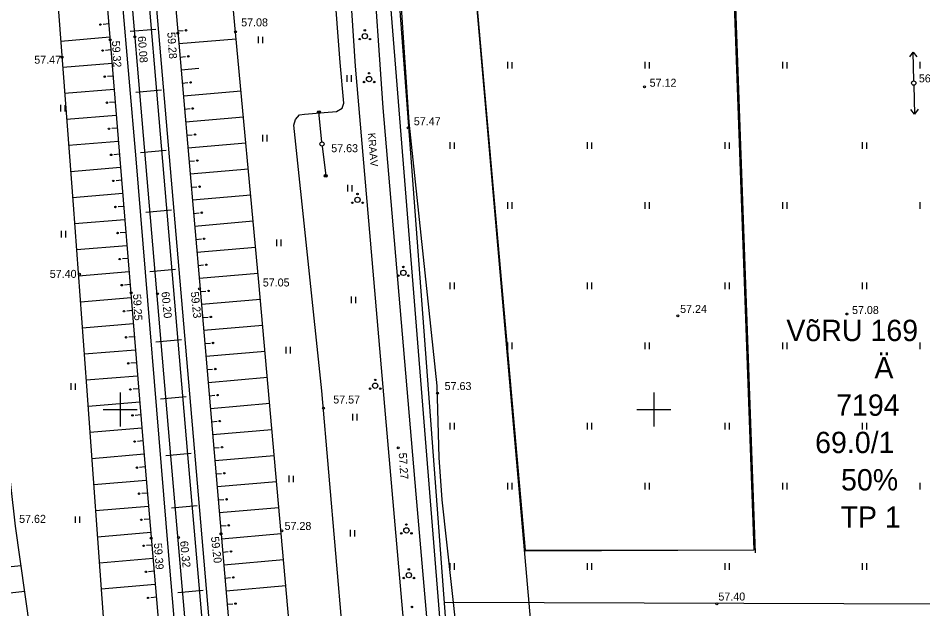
# Model space of a CAD drawing. Extents: x 9156 to 9809, y 2728 to 4000.
# Drawn here: x 9290.4 to 9375.2, y 3581.3 to 3636.7 of the extents above; entities that cross this region are included whole.
import ezdxf

# ---------------------------------------------------------------- set-up
doc = ezdxf.new("R2010")
doc.units = 0
for name, color, linetype in [('Level 1', 7, 'Continuous'), ('Level 11', 7, 'Continuous'), ('Level 5', 7, 'Continuous'), ('Level 54', 7, 'Continuous'), ('Level 58', 7, 'Continuous'), ('Level 6', 7, 'Continuous'), ('Level 7', 7, 'Continuous')]:
    doc.layers.add(name, color=color, linetype=linetype)

# ---------------------------------------------------------------- blocks, each defined once
blk = doc.blocks.new('KKOL')
at = {"layer": 'Level 58'}
for p, q in [((0, 1.59349), (0, -1.5935)), ((-1.5935, 0), (1.59349, 0))]:
    blk.add_line(p, q, dxfattribs=at)

msp = doc.modelspace()

# ---------------------------------------------------------------- linework, layer by layer
at = {"layer": 'Level 1'}
msp.add_line((9347.38, 3362.85), (9317.65, 3734.12), dxfattribs=at)
msp.add_line((9347.38, 3362.85), (9317.65, 3734.12), dxfattribs=at)
at = {"layer": 'Level 11'}
for points in [[(9328.17, 3697.177), (9337.927, 3586.83), (9359.389, 3586.857), (9356.831, 3657.924), (9386.375, 3658.386), (9385.932, 3691.773)], [(9328.17, 3697.177), (9337.927, 3586.771), (9359.389, 3586.857), (9356.831, 3657.924), (9386.375, 3658.386), (9385.932, 3691.773)]]:
    msp.add_lwpolyline(points, close=True, dxfattribs=at)
at = {"layer": 'Level 54'}
for p, q in [((9297.624, 3704.585), (9307.22, 3593.093)), ((9301.488, 3623.507), (9296.984, 3675.228)), ((9325.553, 3648.898), (9327.039, 3626.936)), ((9298.927, 3636.154), (9298.403, 3636.11)), ((9294.421, 3634.544), (9299.03, 3634.932)), ((9300.927, 3635.459), (9303.326, 3635.676)), ((9305.386, 3635.494), (9305.909, 3635.539)), ((9312.93, 3634.964), (9312.93, 3634.344)), ((9313.335, 3634.953), (9313.335, 3634.344)), ((9310.868, 3634.737), (9305.491, 3634.273)), ((9299.13, 3633.711), (9298.606, 3633.668)), ((9373.976, 3633.063), (9374.301, 3633.507)), ((9374.341, 3630.807), (9374.301, 3633.507)), ((9374.301, 3633.507), (9374.638, 3633.073)), ((9294.607, 3632.111), (9299.23, 3632.49)), ((9305.597, 3633.052), (9306.121, 3633.097)), ((9336.272, 3632.595), (9336.272, 3631.975)), ((9336.677, 3632.584), (9336.677, 3631.975)), ((9349.153, 3632.595), (9349.153, 3631.975)), ((9349.559, 3632.584), (9349.559, 3631.975)), ((9362.035, 3632.595), (9362.035, 3631.975)), ((9362.44, 3632.584), (9362.44, 3631.975)), ((9374.916, 3632.595), (9374.916, 3631.975)), ((9307.37, 3631.975), (9305.702, 3631.831)), ((9299.33, 3631.268), (9298.806, 3631.225)), ((9305.808, 3630.61), (9306.332, 3630.655)), ((9321.223, 3631.351), (9321.223, 3630.731)), ((9321.629, 3631.34), (9321.629, 3630.731)), ((9294.793, 3629.667), (9299.43, 3630.047)), ((9301.466, 3629.759), (9303.865, 3629.976)), ((9311.322, 3629.856), (9305.913, 3629.389)), ((9374.35, 3630.407), (9374.424, 3627.708)), ((9294.407, 3628.561), (9294.407, 3627.941)), ((9294.812, 3628.549), (9294.812, 3627.941)), ((9299.53, 3628.825), (9299.006, 3628.782)), ((9306.019, 3628.167), (9306.543, 3628.213)), ((9374.424, 3627.708), (9374.081, 3628.138)), ((9374.743, 3628.156), (9374.424, 3627.708)), ((9294.979, 3627.223), (9299.63, 3627.604)), ((9311.55, 3627.415), (9306.124, 3626.946)), ((9318.885, 3625.098), (9318.614, 3627.885)), ((9327.039, 3626.936), (9329.675, 3602.225)), ((9299.73, 3626.382), (9299.206, 3626.339)), ((9306.23, 3625.725), (9306.754, 3625.771)), ((9313.338, 3625.76), (9313.338, 3625.14)), ((9313.743, 3625.749), (9313.743, 3625.14)), ((9295.165, 3624.779), (9299.83, 3625.161)), ((9311.777, 3624.975), (9306.336, 3624.504)), ((9318.928, 3624.7), (9319.251, 3621.919)), ((9330.866, 3625.064), (9330.866, 3624.444)), ((9331.272, 3625.053), (9331.272, 3624.444)), ((9343.748, 3625.064), (9343.748, 3624.444)), ((9344.153, 3625.053), (9344.153, 3624.444)), ((9356.629, 3625.064), (9356.629, 3624.444)), ((9357.035, 3625.053), (9357.035, 3624.444)), ((9369.511, 3625.064), (9369.511, 3624.444)), ((9369.916, 3625.053), (9369.916, 3624.444)), ((9299.929, 3623.939), (9299.405, 3623.896)), ((9301.906, 3624.108), (9304.305, 3624.325)), ((9304.523, 3586.699), (9301.488, 3623.507)), ((9306.441, 3623.283), (9306.965, 3623.329)), ((9295.351, 3622.335), (9300.029, 3622.718)), ((9312.004, 3622.534), (9306.547, 3622.062)), ((9300.129, 3621.496), (9299.605, 3621.453)), ((9306.652, 3620.841), (9307.176, 3620.887)), ((9321.291, 3621.066), (9321.291, 3620.445)), ((9321.697, 3621.054), (9321.697, 3620.445)), ((9295.538, 3619.891), (9300.229, 3620.275)), ((9312.232, 3620.094), (9306.758, 3619.62)), ((9300.329, 3619.053), (9299.805, 3619.01)), ((9336.272, 3619.444), (9336.272, 3618.824)), ((9336.677, 3619.433), (9336.677, 3618.824)), ((9349.153, 3619.444), (9349.153, 3618.824)), ((9349.559, 3619.433), (9349.559, 3618.824)), ((9362.035, 3619.444), (9362.035, 3618.824)), ((9362.44, 3619.433), (9362.44, 3618.824)), ((9374.916, 3619.444), (9374.916, 3618.824)), ((9302.396, 3618.506), (9304.795, 3618.724)), ((9306.863, 3618.399), (9307.387, 3618.445)), ((9295.72, 3617.446), (9300.429, 3617.832)), ((9312.459, 3617.653), (9306.969, 3617.178)), ((9294.475, 3616.766), (9294.475, 3616.146)), ((9294.88, 3616.755), (9294.88, 3616.146)), ((9300.529, 3616.61), (9300.005, 3616.567)), ((9295.901, 3615.002), (9300.629, 3615.389)), ((9307.075, 3615.957), (9307.598, 3616.003)), ((9314.629, 3615.952), (9314.629, 3615.332)), ((9315.034, 3615.941), (9315.034, 3615.332)), ((9312.686, 3615.212), (9307.18, 3614.736)), ((9300.729, 3614.167), (9300.205, 3614.124)), ((9296.083, 3612.557), (9300.829, 3612.946)), ((9302.786, 3612.949), (9305.185, 3613.167)), ((9307.286, 3613.515), (9307.809, 3613.561)), ((9312.913, 3612.772), (9307.391, 3612.294)), ((9300.929, 3611.724), (9300.405, 3611.681)), ((9330.866, 3611.913), (9330.866, 3611.293)), ((9331.272, 3611.902), (9331.272, 3611.293)), ((9343.748, 3611.913), (9343.748, 3611.293)), ((9344.153, 3611.902), (9344.153, 3611.293)), ((9356.629, 3611.913), (9356.629, 3611.293)), ((9357.035, 3611.902), (9357.035, 3611.293)), ((9369.511, 3611.913), (9369.511, 3611.293)), ((9369.916, 3611.902), (9369.916, 3611.293)), ((9296.264, 3610.113), (9301.029, 3610.503)), ((9307.497, 3611.073), (9308.021, 3611.118)), ((9313.134, 3610.328), (9307.602, 3609.852)), ((9321.632, 3610.592), (9321.632, 3609.972)), ((9322.038, 3610.581), (9322.038, 3609.972)), ((9301.128, 3609.281), (9300.604, 3609.238)), ((9307.707, 3608.631), (9308.231, 3608.676)), ((9296.445, 3607.668), (9301.228, 3608.06)), ((9313.351, 3607.887), (9307.812, 3607.41)), ((9301.328, 3606.838), (9300.804, 3606.795)), ((9303.325, 3606.364), (9305.724, 3606.582)), ((9307.917, 3606.189), (9308.441, 3606.234)), ((9336.272, 3606.293), (9336.272, 3605.673)), ((9336.677, 3606.282), (9336.677, 3605.673)), ((9349.153, 3606.293), (9349.153, 3605.673)), ((9349.559, 3606.282), (9349.559, 3605.673)), ((9362.035, 3606.293), (9362.035, 3605.673)), ((9362.44, 3606.282), (9362.44, 3605.673)), ((9374.916, 3606.293), (9374.916, 3605.673)), ((9296.626, 3605.224), (9301.428, 3605.617)), ((9313.567, 3605.445), (9308.022, 3604.968)), ((9315.514, 3605.887), (9315.514, 3605.267)), ((9315.919, 3605.876), (9315.919, 3605.267)), ((9301.528, 3604.395), (9301.004, 3604.352)), ((9308.127, 3603.747), (9308.651, 3603.792)), ((9296.807, 3602.779), (9301.628, 3603.174)), ((9313.784, 3603.004), (9308.232, 3602.526)), ((9295.358, 3602.474), (9295.358, 3601.854)), ((9295.764, 3602.462), (9295.764, 3601.854)), ((9301.728, 3601.952), (9301.204, 3601.909)), ((9329.675, 3602.225), (9329.847, 3595.503)), ((9300, 3601.25), (9300, 3598.75)), ((9303.766, 3601.008), (9306.165, 3601.226)), ((9308.337, 3601.305), (9308.861, 3601.35)), ((9350, 3601.25), (9350, 3598.75)), ((9296.985, 3600.335), (9301.828, 3600.731)), ((9314.001, 3600.562), (9308.442, 3600.084)), ((9298.75, 3600), (9301.25, 3600)), ((9301.928, 3599.509), (9301.404, 3599.466)), ((9321.768, 3599.615), (9321.768, 3598.995)), ((9322.173, 3599.604), (9322.173, 3598.995)), ((9348.75, 3600), (9351.25, 3600)), ((9308.548, 3598.863), (9309.071, 3598.908)), ((9330.866, 3598.762), (9330.866, 3598.142)), ((9331.272, 3598.75), (9331.272, 3598.142)), ((9343.748, 3598.762), (9343.748, 3598.142)), ((9344.153, 3598.75), (9344.153, 3598.142)), ((9356.629, 3598.762), (9356.629, 3598.142)), ((9357.035, 3598.75), (9357.035, 3598.142)), ((9369.511, 3598.762), (9369.511, 3598.142)), ((9369.916, 3598.75), (9369.916, 3598.142)), ((9297.162, 3597.89), (9302.028, 3598.288)), ((9314.217, 3598.121), (9308.653, 3597.642)), ((9302.128, 3597.066), (9301.604, 3597.021)), ((9304.256, 3595.701), (9306.655, 3595.919)), ((9308.758, 3596.421), (9309.282, 3596.466)), ((9297.34, 3595.424), (9302.233, 3595.845)), ((9314.434, 3595.679), (9308.863, 3595.2)), ((9329.847, 3595.503), (9330.133, 3591.538)), ((9302.338, 3594.624), (9301.815, 3594.579)), ((9297.516, 3592.979), (9302.444, 3593.403)), ((9308.968, 3593.978), (9309.492, 3594.024)), ((9315.786, 3593.82), (9315.786, 3593.2)), ((9316.191, 3593.809), (9316.191, 3593.2)), ((9314.651, 3593.237), (9309.073, 3592.757)), ((9336.272, 3593.142), (9336.272, 3592.521)), ((9336.677, 3593.13), (9336.677, 3592.521)), ((9349.153, 3593.142), (9349.153, 3592.521)), ((9349.559, 3593.13), (9349.559, 3592.521)), ((9362.035, 3593.142), (9362.035, 3592.521)), ((9362.44, 3593.13), (9362.44, 3592.521)), ((9374.916, 3593.142), (9374.916, 3592.521)), ((9302.549, 3592.182), (9302.025, 3592.137)), ((9297.693, 3590.534), (9302.654, 3590.961)), ((9304.795, 3590.787), (9307.194, 3591.005)), ((9309.178, 3591.536), (9309.702, 3591.581)), ((9314.867, 3590.796), (9309.283, 3590.315)), ((9330.133, 3591.538), (9331.678, 3577.558)), ((9295.766, 3589.997), (9295.766, 3589.377)), ((9296.172, 3589.986), (9296.172, 3589.377)), ((9302.759, 3589.74), (9302.235, 3589.695)), ((9309.388, 3589.094), (9309.912, 3589.139)), ((9297.87, 3588.089), (9302.865, 3588.519)), ((9315.084, 3588.354), (9309.493, 3587.873)), ((9321.535, 3588.725), (9321.535, 3588.105)), ((9321.941, 3588.714), (9321.941, 3588.105)), ((9302.97, 3587.298), (9302.446, 3587.253)), ((9307.95, 3547.291), (9304.523, 3586.699)), ((9309.598, 3586.652), (9310.122, 3586.697)), ((9298.046, 3585.644), (9303.075, 3586.077)), ((9315.301, 3585.913), (9309.704, 3585.431)), ((9290.721, 3585.374), (9282.2, 3584.493)), ((9330.866, 3585.61), (9330.866, 3584.99)), ((9331.272, 3585.599), (9331.272, 3584.99)), ((9343.748, 3585.61), (9343.748, 3584.99)), ((9344.153, 3585.599), (9344.153, 3584.99)), ((9356.629, 3585.61), (9356.629, 3584.99)), ((9357.035, 3585.599), (9357.035, 3584.99)), ((9369.511, 3585.61), (9369.511, 3584.99)), ((9369.916, 3585.599), (9369.916, 3584.99)), ((9303.18, 3584.856), (9302.656, 3584.811)), ((9309.809, 3584.21), (9310.332, 3584.255)), ((9298.223, 3583.199), (9303.285, 3583.635)), ((9315.517, 3583.471), (9309.914, 3582.989)), ((9291.061, 3582.945), (9282.452, 3582.055)), ((9303.391, 3582.414), (9302.867, 3582.369)), ((9305.381, 3582.857), (9307.78, 3583.075)), ((9310.019, 3581.768), (9310.543, 3581.813))]:
    msp.add_line(p, q, dxfattribs=at)
for points in [[(9291.142, 3750), (9292.509, 3734.326), (9298.237, 3671.484), (9304.697, 3595.661), (9311.403, 3518.763), (9313.026, 3500)], [(9292.749, 3750), (9294.103, 3734.468), (9299.832, 3671.625), (9306.292, 3595.799), (9312.998, 3518.901), (9314.633, 3500)], [(9289.521, 3722.865), (9289.636, 3711.949), (9290.094, 3696.436), (9293.302, 3649.242), (9295.59, 3619.198), (9296.851, 3602.192), (9300.163, 3556.342), (9301.424, 3542.094), (9302.684, 3538.991), (9304.632, 3528.075), (9306.915, 3513.758), (9308.634, 3504.221), (9309.025, 3500)], [(9291.411, 3723.027), (9293.543, 3697.334), (9296.97, 3659.378), (9299.033, 3634.903), (9302.12, 3597.158), (9303.724, 3578.543), (9308.876, 3518.425), (9310.547, 3500)], [(9298.789, 3500), (9298.217, 3515.72), (9298.103, 3526.407), (9296.155, 3540.196), (9294.785, 3549.211), (9292.952, 3569.435), (9290.202, 3589.084), (9286.767, 3619.468), (9285.736, 3621.307), (9285.048, 3622.915), (9284.705, 3624.754), (9285.736, 3627.512), (9286.423, 3629.465), (9282.989, 3666.871), (9279.667, 3687.502), (9279.324, 3696.006), (9278.522, 3701.406), (9275.886, 3702.9), (9273.137, 3704.049)], [(9338.258, 3687.747), (9322.788, 3689.022), (9307.371, 3689.607), (9301.808, 3689.766), (9301.118, 3689.66), (9300.588, 3689.394), (9305.358, 3635.801), (9307.477, 3611.291), (9311.555, 3563.906), (9317.681, 3500)], [(9322.827, 3500), (9320.981, 3519.574), (9317.172, 3564.824), (9312.99, 3611.945), (9310.716, 3636.371), (9308.332, 3662.194), (9306.003, 3685.955), (9306.268, 3686.115), (9314.533, 3685.69)], [(9320.59, 3632.541), (9317.733, 3670.104), (9317.548, 3671.911), (9317.044, 3672.043), (9314.131, 3672.043), (9313.177, 3672.309), (9312.647, 3673.903), (9312.753, 3675.869), (9313.548, 3676.56), (9315.084, 3676.56), (9316.991, 3676.772), (9317.415, 3677.729), (9316.938, 3683.892)], [(9318.454, 3683.747), (9319.718, 3666.857), (9322.009, 3632.198), (9324.759, 3600.294), (9328.879, 3553.079), (9332.486, 3509.644), (9333.576, 3500)], [(9335.945, 3500), (9334.833, 3509.401), (9333.86, 3522.52), (9332.198, 3540.675), (9327.731, 3592.08), (9324.641, 3628.274), (9322.58, 3658.051), (9320.287, 3683.565)], [(9316.248, 3626.653), (9316.408, 3627.198), (9316.805, 3627.623), (9317.256, 3627.703), (9319.11, 3627.862), (9320.249, 3627.942), (9320.779, 3628.26), (9320.938, 3628.739), (9320.59, 3632.541)], [(9325.777, 3525.127), (9323.47, 3548.394), (9318.897, 3601.758), (9316.248, 3626.653)], [(9307.22, 3593.093), (9313.584, 3518.487), (9315.454, 3500)]]:
    msp.add_lwpolyline(points, dxfattribs=at)
for centre, radius in [((9298.148, 3636.096), 0.0683), ((9301.374, 3634.935), 0.0909), ((9305.384, 3635.276), 0.0909), ((9306.165, 3635.553), 0.0683), ((9310.793, 3635.406), 0.0909), ((9322.916, 3635.003), 0.25), ((9322.916, 3635.553), 0.0707), ((9299.062, 3634.662), 0.0909), ((9322.439, 3634.728), 0.0707), ((9323.392, 3634.728), 0.0707), ((9298.351, 3633.655), 0.0683), ((9306.376, 3633.111), 0.0683), ((9294.542, 3633.026), 0.0909), ((9323.317, 3631.531), 0.0707), ((9298.551, 3631.212), 0.0683), ((9306.587, 3630.669), 0.0683), ((9322.84, 3630.706), 0.0707), ((9323.317, 3630.981), 0.25), ((9323.793, 3630.706), 0.0707), ((9374.344, 3630.607), 0.2), ((9374.344, 3630.607), 0.2), ((9349.123, 3630.265), 0.0909), ((9298.75, 3628.769), 0.0683), ((9306.798, 3628.227), 0.0683), ((9318.614, 3627.885), 0.136), ((9318.614, 3627.885), 0.121), ((9318.614, 3627.885), 0.107), ((9318.614, 3627.885), 0.0902), ((9318.614, 3627.885), 0.0749), ((9318.614, 3627.885), 0.0616), ((9318.614, 3627.885), 0.0468), ((9318.614, 3627.885), 0.0343), ((9318.614, 3627.885), 0.0209), ((9318.614, 3627.885), 0.0112), ((9326.972, 3626.404), 0.0909), ((9298.95, 3626.326), 0.0683), ((9307.009, 3625.785), 0.0683), ((9318.905, 3624.899), 0.2), ((9318.905, 3624.899), 0.2), ((9299.15, 3623.883), 0.0683), ((9307.22, 3623.343), 0.0683), ((9299.35, 3621.44), 0.0683), ((9319.251, 3621.919), 0.136), ((9319.251, 3621.919), 0.121), ((9319.251, 3621.919), 0.107), ((9319.251, 3621.919), 0.0902), ((9319.251, 3621.919), 0.0749), ((9319.251, 3621.919), 0.0616), ((9319.251, 3621.919), 0.0468), ((9319.251, 3621.919), 0.0343), ((9319.251, 3621.919), 0.0209), ((9319.251, 3621.919), 0.0112), ((9307.431, 3620.901), 0.0683), ((9322.228, 3619.663), 0.25), ((9322.228, 3620.213), 0.0707), ((9299.55, 3618.997), 0.0683), ((9321.752, 3619.388), 0.0707), ((9322.704, 3619.388), 0.0707), ((9307.642, 3618.459), 0.0683), ((9299.75, 3616.554), 0.0683), ((9307.854, 3616.017), 0.0683), ((9299.949, 3614.111), 0.0683), ((9308.065, 3613.575), 0.0683), ((9326.525, 3612.826), 0.25), ((9326.525, 3613.376), 0.0707), ((9296.172, 3612.708), 0.0909), ((9326.048, 3612.551), 0.0707), ((9327.001, 3612.551), 0.0707), ((9300.149, 3611.668), 0.0683), ((9307.423, 3611.311), 0.0909), ((9308.276, 3611.133), 0.0683), ((9301.032, 3610.936), 0.0909), ((9303.48, 3610.868), 0.0909), ((9300.349, 3609.225), 0.0683), ((9308.486, 3608.691), 0.0683), ((9352.25, 3608.789), 0.0909), ((9368.067, 3608.963), 0.0909), ((9300.549, 3606.782), 0.0683), ((9308.696, 3606.249), 0.0683), ((9300.749, 3604.339), 0.0683), ((9308.906, 3603.806), 0.0683), ((9323.887, 3602.789), 0.0707), ((9300.949, 3601.896), 0.0683), ((9323.411, 3601.964), 0.0707), ((9323.887, 3602.239), 0.25), ((9324.364, 3601.964), 0.0707), ((9309.116, 3601.364), 0.0683), ((9329.725, 3601.546), 0.0909), ((9319.052, 3600.149), 0.0909), ((9301.148, 3599.453), 0.0683), ((9309.327, 3598.922), 0.0683), ((9301.349, 3597.007), 0.0683), ((9309.537, 3596.48), 0.0683), ((9326.051, 3596.409), 0.0909), ((9301.559, 3594.565), 0.0683), ((9309.747, 3594.038), 0.0683), ((9301.77, 3592.123), 0.0683), ((9309.957, 3591.596), 0.0683), ((9301.98, 3589.68), 0.0683), ((9310.167, 3589.154), 0.0683), ((9326.809, 3589.23), 0.0707), ((9309.438, 3588.353), 0.0909), ((9315.147, 3588.649), 0.0909), ((9326.333, 3588.405), 0.0707), ((9326.809, 3588.68), 0.25), ((9327.285, 3588.405), 0.0707), ((9302.891, 3587.958), 0.0909), ((9305.451, 3588.007), 0.0909), ((9302.191, 3587.238), 0.0683), ((9310.377, 3586.712), 0.0683), ((9302.401, 3584.796), 0.0683), ((9327.038, 3585.036), 0.0707), ((9310.588, 3584.27), 0.0683), ((9326.562, 3584.211), 0.0707), ((9327.038, 3584.486), 0.25), ((9327.515, 3584.211), 0.0707), ((9302.612, 3582.354), 0.0683), ((9310.798, 3581.827), 0.0683), ((9327.322, 3581.507), 0.0707), ((9355.887, 3581.807), 0.0909)]:
    msp.add_circle(centre, radius, dxfattribs=at)
at = {"layer": 'Level 6'}
for p, q in [((9306.372, 3945.862), (9356.727, 3371.389)), ((9356.909, 3657.786), (9359.471, 3586.582))]:
    msp.add_line(p, q, dxfattribs=at)
at = {"layer": 'Level 7'}
for p, q in [((9322.45, 3687.11), (9329.751, 3589.839)), ((9329.751, 3589.839), (9336.15, 3503.09)), ((9330.333, 3581.943), (9387.779, 3581.775))]:
    msp.add_line(p, q, dxfattribs=at)

# ---------------------------------------------------------------- block references
at = {"layer": 'Level 54'}
for p in [(9300, 3600), (9350, 3600)]:
    msp.add_blockref('KKOL', p, dxfattribs=at)

# ---------------------------------------------------------------- texts
at = {"layer": 'Level 5'}
for s, p in [('VõRU 169', (9362.408, 3606.425)), ('Ä', (9370.655, 3602.925)), ('7194', (9367.067, 3599.425)), ('69.0/1', (9365.102, 3595.925)), ('50%', (9367.527, 3592.425)), ('TP 1', (9367.483, 3588.925))]:
    msp.add_text(s, height=2, dxfattribs=at).set_placement(p)
at = {"layer": 'Level 54'}
for s, p in [('57.08', (9311.33, 3635.925)), ('57.47', (9291.948, 3632.427)), ('57.12', (9349.599, 3630.265)), ('56.97', (9374.82, 3630.674)), ('57.47', (9327.505, 3626.652)), ('57.63', (9319.768, 3624.129)), ('57.40', (9293.397, 3612.35)), ('57.05', (9313.355, 3611.544)), ('57.24', (9352.454, 3609.062)), ('57.08', (9368.558, 3608.963)), ('57.63', (9330.391, 3601.836)), ('57.57', (9319.956, 3600.575)), ('57.62', (9290.527, 3589.387)), ('57.28', (9315.394, 3588.722)), ('57.40', (9356.04, 3582.107))]:
    msp.add_text(s, height=0.75, dxfattribs=at).set_placement(p)
for s, height, rotation, p in [('60.08', 0.75, 274.62205, (9301.64, 3634.984)), ('59.28', 0.75, 274.19396, (9304.4, 3635.353)), ('59.32', 0.75, 273.40693, (9299.216, 3634.557)), ('KRAAV', 0.7, 274.56071, (9323.202, 3625.916)), ('59.25', 0.75, 273.00405, (9301.195, 3610.833)), ('60.20', 0.75, 275.69424, (9303.857, 3611.025)), ('59.23', 0.75, 276.18555, (9306.595, 3611.022)), ('57.27', 0.75, 273.8037, (9326.089, 3595.937)), ('59.39', 0.75, 274.13255, (9303.153, 3587.479)), ('60.32', 0.75, 275.79005, (9305.601, 3587.657)), ('59.20', 0.75, 276.56306, (9308.494, 3588.063))]:
    msp.add_text(s, height=height, rotation=rotation, dxfattribs=at).set_placement(p)

doc.saveas('drawing.dxf')
